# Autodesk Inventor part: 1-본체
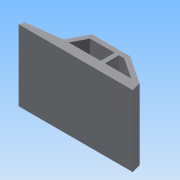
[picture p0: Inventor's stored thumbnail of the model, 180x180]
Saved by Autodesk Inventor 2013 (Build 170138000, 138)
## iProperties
Created: 2015-05
Part Number: 1-본체
Material: 일반
Document SubType Name: Modeling
Designer: Administrator
Density: 1 g/cm^3
Author: Administrator
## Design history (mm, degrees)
sketch "스케치1"
  geometry: L1 (-61, 0)-(61, 0); L2 (-61, 0)-(-59.66, 5); L3 (-12.679, 30)-(28.321, 30); L4 (28.321, 30)-(58.321, 10); L5 (58.321, 10)-(61, 0); L6 (-59.66, 5)-(-22.975, 10); L7 (-22.975, 10)-(-12.679, 30); 2 further points
  constraints: 14 end point, 1 coincident, 1 horizontal, 1 midpoint, 1 parallel
  dimensions: "d1" = 122 distance of L1.start L1.end; "d13" = 30 vertical distance of L1.end L3.end; "d14" = 105 deg angle of L1 L5; "d15" = 30 horizontal distance of L4.end L3.end; "d16" = 20 vertical distance of L4.end L3.end; "d17" = 41 distance of L3.start L3.end; "d27" = 5 vertical distance of L2.end L1.start; "d28" = 105 deg angle of L1 L2; "d30" = 125 deg angle of L7 L6; "d31" = 20 vertical distance of L3.start L6.end
extrude "돌출1" new body sketch "스케치1" distance "d18" = 76; taper "d19" = 0 deg
sketch "스케치3"
  geometry: L1 (58.321, 10)-(28.321, 30) reference; L2 (28.321, 30)-(-12.679, 30) reference; L3 (-12.679, 30)-(-22.975, 10) reference; L4 (-9.63, 25)-(16.648, 25); L5 (16.648, 25)-(16.648, 10); L6 (16.648, 10)-(-17.352, 10); L7 (-17.352, 10)-(-9.63, 25); L8 (21.307, 25)-(21.307, 10); L9 (21.307, 10)-(49.307, 10); L10 (49.307, 10)-(26.807, 25); L11 (26.807, 25)-(21.307, 25); 1 further point
  constraints: 16 end point, 5 parallel, 3 perpendicular, 1 collinear, 1 point on line
  dimensions: "d32" = 15 vertical distance of L6.end L4.start; "d34" = 34 distance of L5.end L6.end; "d36" = 5 distance between parallel lines of L3 L7; "d37" = 5 distance between parallel lines of L4 L2; "d38" = 28 distance of L8.end L9.end; "d39" = 5 distance between parallel lines of L10 L1
extrude "돌출2" cut sketch "스케치3" stored distance "d40" = 76; taper "d41" = 0 deg
node "작업 평면1"
sketch "스케치5"
  geometry: L1 (-22.975, 10)-(-59.66, 5) reference; L2 (-31.423, 13.895)-(-47.633, 11.685); L3 (-31.423, 13.895)-(-28.944, 9.186); L4 (-47.633, 11.685)-(-48.761, 6.486); L5 (-59.66, 5)-(-61, 0) reference; 1 further point
  constraints: 6 end point, 2 point on line, 1 parallel
  dimensions: "d51" = 70 deg angle of L1 L3; "d52" = 70 deg angle of L1 L4; "d53" = 20 distance of L3.end L4.end; "d55" = 11 distance of L1.end L4.end; "d56" = 5 distance between parallel lines of L1 L2
extrude "돌출3" join sketch "스케치5" stored distance "d57" = 26; taper "d58" = 0 deg
sketch "스케치6"
  geometry: L1 (41, 0)-(41, -76) reference; L2 (73.679, 0)-(73.679, -76) reference; 3 further points
  constraints: 1 horizontal alignment, 1 midpoint, 1 other
  dimensions: "d59" = 50 distance from line of L2 point (23.679, -38)
feature "엠보싱1" sketch "스케치6" dims "d15" = 30, "d32" = 15, "d34" = 34, "d36" = 5, "d37" = 5, "d38" = 28, "d39" = 5, "d60" = 0.5, "d61" = 0
node "솔리드1"
